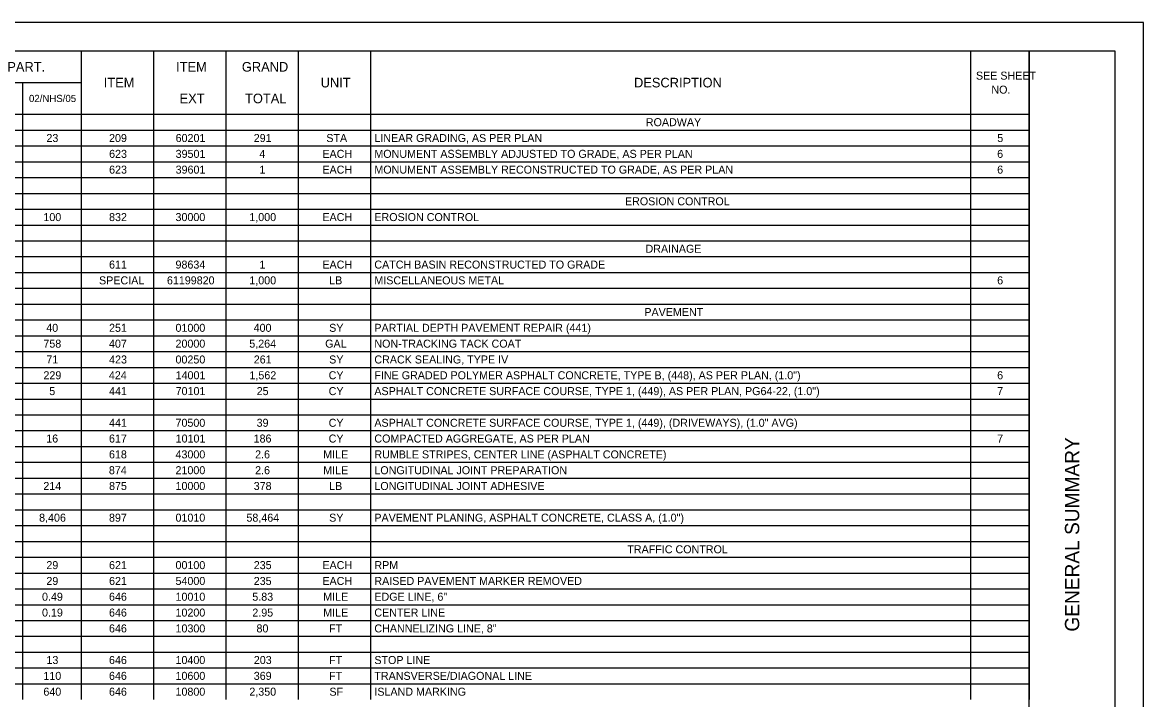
# Model space of a CAD drawing. Extents: x 0 to 34, y 0 to 22.
# Drawn here: x 14.4 to 34, y 10.16 to 22 of the extents above; entities that cross this region are included whole.
import ezdxf

# ---------------------------------------------------------------- set-up
doc = ezdxf.new("R2010")
doc.units = 0
for name, color, linetype in [('Default', 7, 'Continuous'), ('SH_Border', 7, 'Continuous'), ('SH_Cut_Line', 7, 'Continuous'), ('SH_Data', 7, 'Continuous')]:
    doc.layers.add(name, color=color, linetype=linetype)

msp = doc.modelspace()

# ---------------------------------------------------------------- linework, layer by layer
at = {"layer": 'Default'}
for p, q in [((13.368, 21.5), (14.396, 21.5)), ((14.396, 21.5), (30.972, 21.5)), ((15.424, 21.5), (15.424, 21.223)), ((16.689, 21.5), (16.689, 21.223)), ((17.954, 21.5), (17.954, 21.223)), ((19.219, 21.5), (19.219, 21.223)), ((20.484, 21.5), (20.484, 21.223)), ((30.972, 21.5), (32, 21.5)), ((30.972, 21.5), (30.972, 21.223)), ((32, 21.5), (32, 21.223)), ((15.424, 21.223), (15.424, 20.947)), ((16.689, 21.223), (16.689, 20.947)), ((17.954, 21.223), (17.954, 20.947)), ((19.219, 21.223), (19.219, 20.947)), ((20.484, 21.223), (20.484, 20.947)), ((30.972, 21.223), (30.972, 20.947)), ((32, 21.223), (32, 20.947)), ((13.368, 20.947), (14.396, 20.947)), ((14.396, 20.947), (15.424, 20.947)), ((14.396, 20.947), (14.396, 20.67)), ((15.424, 20.947), (15.424, 20.67)), ((16.689, 20.947), (16.689, 20.67)), ((17.954, 20.947), (17.954, 20.67)), ((19.219, 20.947), (19.219, 20.67)), ((20.484, 20.947), (20.484, 20.67)), ((30.972, 20.947), (30.972, 20.67)), ((32, 20.947), (32, 20.67)), ((14.396, 20.67), (14.396, 20.393)), ((15.424, 20.67), (15.424, 20.393)), ((16.689, 20.67), (16.689, 20.393)), ((17.954, 20.67), (17.954, 20.393)), ((19.219, 20.67), (19.219, 20.393)), ((20.484, 20.67), (20.484, 20.393)), ((30.972, 20.67), (30.972, 20.393)), ((32, 20.67), (32, 20.393)), ((13.368, 20.393), (14.396, 20.393)), ((14.396, 20.393), (30.972, 20.393)), ((14.396, 20.393), (14.396, 20.116)), ((15.424, 20.393), (15.424, 20.116)), ((16.689, 20.393), (16.689, 20.116)), ((17.954, 20.393), (17.954, 20.116)), ((19.219, 20.393), (19.219, 20.116)), ((20.484, 20.393), (20.484, 20.116)), ((30.972, 20.393), (32, 20.393)), ((30.972, 20.393), (30.972, 20.116)), ((32, 20.393), (32, 20.116)), ((13.368, 20.116), (14.396, 20.116)), ((14.396, 20.116), (30.972, 20.116)), ((14.396, 20.116), (14.396, 18.733)), ((15.424, 20.116), (15.424, 18.733)), ((16.689, 20.116), (16.689, 18.733)), ((17.954, 20.116), (17.954, 18.733)), ((19.219, 20.116), (19.219, 18.733)), ((20.484, 20.116), (20.484, 18.733)), ((30.972, 20.116), (32, 20.116)), ((30.972, 20.116), (30.972, 18.733)), ((32, 20.116), (32, 18.733)), ((13.368, 19.84), (14.396, 19.84)), ((14.396, 19.84), (30.972, 19.84)), ((30.972, 19.84), (32, 19.84)), ((13.368, 19.563), (14.396, 19.563)), ((14.396, 19.563), (30.972, 19.563)), ((30.972, 19.563), (32, 19.563)), ((13.368, 19.286), (14.396, 19.286)), ((14.396, 19.286), (30.972, 19.286)), ((30.972, 19.286), (32, 19.286)), ((13.368, 19.01), (14.396, 19.01)), ((14.396, 19.01), (30.972, 19.01)), ((30.972, 19.01), (32, 19.01)), ((13.368, 18.733), (14.396, 18.733)), ((14.396, 18.733), (30.972, 18.733)), ((14.396, 18.733), (14.396, 18.18)), ((15.424, 18.733), (15.424, 18.18)), ((16.689, 18.733), (16.689, 18.18)), ((17.954, 18.733), (17.954, 18.18)), ((19.219, 18.733), (19.219, 18.18)), ((20.484, 18.733), (20.484, 18.18)), ((30.972, 18.733), (32, 18.733)), ((30.972, 18.733), (30.972, 18.18)), ((32, 18.733), (32, 18.18)), ((13.368, 18.456), (14.396, 18.456)), ((14.396, 18.456), (30.972, 18.456)), ((30.972, 18.456), (32, 18.456)), ((13.368, 18.18), (14.396, 18.18)), ((14.396, 18.18), (30.972, 18.18)), ((14.396, 18.18), (14.396, 17.903)), ((15.424, 18.18), (15.424, 17.903)), ((16.689, 18.18), (16.689, 17.903)), ((17.954, 18.18), (17.954, 17.903)), ((19.219, 18.18), (19.219, 17.903)), ((20.484, 18.18), (20.484, 17.903)), ((30.972, 18.18), (32, 18.18)), ((30.972, 18.18), (30.972, 17.903)), ((32, 18.18), (32, 17.903)), ((13.368, 17.903), (14.396, 17.903)), ((14.396, 17.903), (30.972, 17.903)), ((14.396, 17.903), (14.396, 17.626)), ((15.424, 17.903), (15.424, 17.626)), ((16.689, 17.903), (16.689, 17.626)), ((17.954, 17.903), (17.954, 17.626)), ((19.219, 17.903), (19.219, 17.626)), ((20.484, 17.903), (20.484, 17.626)), ((30.972, 17.903), (32, 17.903)), ((30.972, 17.903), (30.972, 17.626)), ((32, 17.903), (32, 17.626)), ((13.368, 17.626), (14.396, 17.626)), ((14.396, 17.626), (30.972, 17.626)), ((14.396, 17.626), (14.396, 17.349)), ((15.424, 17.626), (15.424, 17.349)), ((16.689, 17.626), (16.689, 17.349)), ((17.954, 17.626), (17.954, 17.349)), ((19.219, 17.626), (19.219, 17.349)), ((20.484, 17.626), (20.484, 17.349)), ((30.972, 17.626), (32, 17.626)), ((30.972, 17.626), (30.972, 17.349)), ((32, 17.626), (32, 17.349)), ((13.368, 17.349), (14.396, 17.349)), ((14.396, 17.349), (30.972, 17.349)), ((14.396, 17.349), (14.396, 17.073)), ((15.424, 17.349), (15.424, 17.073)), ((16.689, 17.349), (16.689, 17.073)), ((17.954, 17.349), (17.954, 17.073)), ((19.219, 17.349), (19.219, 17.073)), ((20.484, 17.349), (20.484, 17.073)), ((30.972, 17.349), (32, 17.349)), ((30.972, 17.349), (30.972, 17.073)), ((32, 17.349), (32, 17.073)), ((13.368, 17.073), (14.396, 17.073)), ((14.396, 17.073), (30.972, 17.073)), ((14.396, 17.073), (14.396, 16.796)), ((15.424, 17.073), (15.424, 16.796)), ((16.689, 17.073), (16.689, 16.796)), ((17.954, 17.073), (17.954, 16.796)), ((19.219, 17.073), (19.219, 16.796)), ((20.484, 17.073), (20.484, 16.796)), ((30.972, 17.073), (32, 17.073)), ((30.972, 17.073), (30.972, 16.796)), ((32, 17.073), (32, 16.796)), ((13.368, 16.796), (14.396, 16.796)), ((14.396, 16.796), (30.972, 16.796)), ((14.396, 16.796), (14.396, 16.243)), ((15.424, 16.796), (15.424, 16.243)), ((16.689, 16.796), (16.689, 16.243)), ((17.954, 16.796), (17.954, 16.243)), ((19.219, 16.796), (19.219, 16.243)), ((20.484, 16.796), (20.484, 16.243)), ((30.972, 16.796), (32, 16.796)), ((30.972, 16.796), (30.972, 16.243)), ((32, 16.796), (32, 16.243)), ((13.368, 16.519), (14.396, 16.519)), ((14.396, 16.519), (30.972, 16.519)), ((30.972, 16.519), (32, 16.519)), ((13.368, 16.243), (14.396, 16.243)), ((14.396, 16.243), (30.972, 16.243)), ((14.396, 16.243), (14.396, 15.966)), ((15.424, 16.243), (15.424, 15.966)), ((16.689, 16.243), (16.689, 15.966)), ((17.954, 16.243), (17.954, 15.966)), ((19.219, 16.243), (19.219, 15.966)), ((20.484, 16.243), (20.484, 15.966)), ((30.972, 16.243), (32, 16.243)), ((30.972, 16.243), (30.972, 15.966)), ((32, 16.243), (32, 15.966)), ((13.368, 15.966), (14.396, 15.966)), ((14.396, 15.966), (30.972, 15.966)), ((14.396, 15.966), (14.396, 15.689)), ((15.424, 15.966), (15.424, 15.689)), ((16.689, 15.966), (16.689, 15.689)), ((17.954, 15.966), (17.954, 15.689)), ((19.219, 15.966), (19.219, 15.689)), ((20.484, 15.966), (20.484, 15.689)), ((30.972, 15.966), (32, 15.966)), ((30.972, 15.966), (30.972, 15.689)), ((32, 15.966), (32, 15.689)), ((13.368, 15.689), (14.396, 15.689)), ((14.396, 15.689), (30.972, 15.689)), ((14.396, 15.689), (14.396, 15.412)), ((15.424, 15.689), (15.424, 15.412)), ((16.689, 15.689), (16.689, 15.412)), ((17.954, 15.689), (17.954, 15.412)), ((19.219, 15.689), (19.219, 15.412)), ((20.484, 15.689), (20.484, 15.412)), ((30.972, 15.689), (32, 15.689)), ((30.972, 15.689), (30.972, 15.412)), ((32, 15.689), (32, 15.412)), ((13.368, 15.412), (14.396, 15.412)), ((14.396, 15.412), (30.972, 15.412)), ((14.396, 15.412), (14.396, 14.859)), ((15.424, 15.412), (15.424, 14.859)), ((16.689, 15.412), (16.689, 14.859)), ((17.954, 15.412), (17.954, 14.859)), ((19.219, 15.412), (19.219, 14.859)), ((20.484, 15.412), (20.484, 14.859)), ((30.972, 15.412), (32, 15.412)), ((30.972, 15.412), (30.972, 14.859)), ((32, 15.412), (32, 14.859)), ((13.368, 15.136), (14.396, 15.136)), ((14.396, 15.136), (30.972, 15.136)), ((30.972, 15.136), (32, 15.136)), ((13.368, 14.859), (14.396, 14.859)), ((14.396, 14.859), (30.972, 14.859)), ((14.396, 14.859), (14.396, 14.582)), ((15.424, 14.859), (15.424, 14.582)), ((16.689, 14.859), (16.689, 14.582)), ((17.954, 14.859), (17.954, 14.582)), ((19.219, 14.859), (19.219, 14.582)), ((20.484, 14.859), (20.484, 14.582)), ((30.972, 14.859), (32, 14.859)), ((30.972, 14.859), (30.972, 14.582)), ((32, 14.859), (32, 14.582)), ((13.368, 14.582), (14.396, 14.582)), ((14.396, 14.582), (30.972, 14.582)), ((14.396, 14.582), (14.396, 14.306)), ((15.424, 14.582), (15.424, 14.306)), ((16.689, 14.582), (16.689, 14.306)), ((17.954, 14.582), (17.954, 14.306)), ((19.219, 14.582), (19.219, 14.306)), ((20.484, 14.582), (20.484, 14.306)), ((30.972, 14.582), (32, 14.582)), ((30.972, 14.582), (30.972, 14.306)), ((32, 14.582), (32, 14.306)), ((13.368, 14.306), (14.396, 14.306)), ((14.396, 14.306), (30.972, 14.306)), ((14.396, 14.306), (14.396, 14.029)), ((15.424, 14.306), (15.424, 14.029)), ((16.689, 14.306), (16.689, 14.029)), ((17.954, 14.306), (17.954, 14.029)), ((19.219, 14.306), (19.219, 14.029)), ((20.484, 14.306), (20.484, 14.029)), ((30.972, 14.306), (32, 14.306)), ((30.972, 14.306), (30.972, 14.029)), ((32, 14.306), (32, 14.029)), ((13.368, 14.029), (14.396, 14.029)), ((14.396, 14.029), (30.972, 14.029)), ((14.396, 14.029), (14.396, 11.815)), ((15.424, 14.029), (15.424, 11.815)), ((16.689, 14.029), (16.689, 11.815)), ((17.954, 14.029), (17.954, 11.815)), ((19.219, 14.029), (19.219, 11.815)), ((20.484, 14.029), (20.484, 11.815)), ((30.972, 14.029), (32, 14.029)), ((30.972, 14.029), (30.972, 11.815)), ((32, 14.029), (32, 11.815)), ((13.368, 13.752), (14.396, 13.752)), ((14.396, 13.752), (30.972, 13.752)), ((30.972, 13.752), (32, 13.752)), ((13.368, 13.476), (14.396, 13.476)), ((14.396, 13.476), (30.972, 13.476)), ((30.972, 13.476), (32, 13.476)), ((13.368, 13.199), (14.396, 13.199)), ((14.396, 13.199), (30.972, 13.199)), ((30.972, 13.199), (32, 13.199)), ((13.368, 12.922), (14.396, 12.922)), ((14.396, 12.922), (30.972, 12.922)), ((30.972, 12.922), (32, 12.922)), ((13.368, 12.645), (14.396, 12.645)), ((14.396, 12.645), (30.972, 12.645)), ((30.972, 12.645), (32, 12.645)), ((13.368, 12.369), (14.396, 12.369)), ((14.396, 12.369), (30.972, 12.369)), ((30.972, 12.369), (32, 12.369)), ((13.368, 12.092), (14.396, 12.092)), ((14.396, 12.092), (30.972, 12.092)), ((30.972, 12.092), (32, 12.092)), ((13.368, 11.815), (14.396, 11.815)), ((14.396, 11.815), (30.972, 11.815)), ((14.396, 11.815), (14.396, 11.539)), ((15.424, 11.815), (15.424, 11.539)), ((16.689, 11.815), (16.689, 11.539)), ((17.954, 11.815), (17.954, 11.539)), ((19.219, 11.815), (19.219, 11.539)), ((20.484, 11.815), (20.484, 11.539)), ((30.972, 11.815), (32, 11.815)), ((30.972, 11.815), (30.972, 11.539)), ((32, 11.815), (32, 11.539)), ((13.368, 11.539), (14.396, 11.539)), ((14.396, 11.539), (30.972, 11.539)), ((14.396, 11.539), (14.396, 10.432)), ((15.424, 11.539), (15.424, 10.432)), ((16.689, 11.539), (16.689, 10.432)), ((17.954, 11.539), (17.954, 10.432)), ((19.219, 11.539), (19.219, 10.432)), ((20.484, 11.539), (20.484, 10.432)), ((30.972, 11.539), (32, 11.539)), ((30.972, 11.539), (30.972, 10.432)), ((32, 11.539), (32, 10.432)), ((13.368, 11.262), (14.396, 11.262)), ((14.396, 11.262), (30.972, 11.262)), ((30.972, 11.262), (32, 11.262)), ((13.368, 10.985), (14.396, 10.985)), ((14.396, 10.985), (30.972, 10.985)), ((30.972, 10.985), (32, 10.985)), ((13.368, 10.708), (14.396, 10.708)), ((14.396, 10.708), (30.972, 10.708)), ((30.972, 10.708), (32, 10.708)), ((13.368, 10.432), (14.396, 10.432)), ((14.396, 10.432), (30.972, 10.432)), ((14.396, 10.432), (14.396, 10.155)), ((15.424, 10.432), (15.424, 10.155)), ((16.689, 10.432), (16.689, 10.155)), ((17.954, 10.432), (17.954, 10.155)), ((19.219, 10.432), (19.219, 10.155)), ((20.484, 10.432), (20.484, 10.155)), ((30.972, 10.432), (32, 10.432)), ((30.972, 10.432), (30.972, 10.155)), ((32, 10.432), (32, 10.155))]:
    msp.add_line(p, q, dxfattribs=at)
at = {"layer": 'SH_Border'}
msp.add_line((32, 0.5), (32, 21.5), dxfattribs=at)
msp.add_lwpolyline([(1.5, 21.5), (33.5, 21.5), (33.5, 0.5), (1.5, 0.5)], close=True, dxfattribs=at)
at = {"layer": 'SH_Cut_Line'}
msp.add_lwpolyline([(0, 0), (34, 0), (34, 22), (0, 22)], close=True, dxfattribs=at)

# ---------------------------------------------------------------- texts
at = {"layer": 'Default'}
for s, height, p in [('PART.', 0.168, (14.132, 21.139)), ('ITEM', 0.168, (17.083, 21.139)), ('GRAND', 0.168, (18.233, 21.139)), ('ITEM', 0.168, (15.818, 20.863)), ('UNIT', 0.168, (19.611, 20.863)), ('DESCRIPTION', 0.168, (25.09, 20.863)), ('SEE SHEET ', 0.14, (31.069, 20.999)), ('NO.', 0.14, (31.339, 20.754)), ('02/NHS/05', 0.126, (14.511, 20.607)), ('EXT', 0.168, (17.144, 20.586)), ('TOTAL', 0.168, (18.289, 20.586)), ('ROADWAY', 0.14, (25.297, 20.185)), ('23', 0.14, (14.816, 19.908)), ('209', 0.14, (15.911, 19.908)), ('60201', 0.14, (17.075, 19.908)), ('291', 0.14, (18.441, 19.908)), ('STA', 0.14, (19.71, 19.908)), ('LINEAR GRADING, AS PER PLAN', 0.14, (20.55, 19.908)), ('5', 0.14, (31.442, 19.908)), ('623', 0.14, (15.912, 19.631)), ('39501', 0.14, (17.075, 19.631)), ('4', 0.14, (18.539, 19.631)), ('EACH', 0.14, (19.641, 19.631)), ('MONUMENT ASSEMBLY ADJUSTED TO GRADE, AS PER PLAN', 0.14, (20.55, 19.631)), ('6', 0.14, (31.44, 19.631)), ('623', 0.14, (15.912, 19.355)), ('39601', 0.14, (17.075, 19.355)), ('1', 0.14, (18.541, 19.355)), ('EACH', 0.14, (19.641, 19.355)), ('MONUMENT ASSEMBLY RECONSTRUCTED TO GRADE, AS PER PLAN', 0.14, (20.55, 19.355)), ('6', 0.14, (31.44, 19.355)), ('EROSION CONTROL', 0.14, (24.932, 18.801)), ('100', 0.14, (14.763, 18.525)), ('832', 0.14, (15.911, 18.525)), ('30000', 0.14, (17.073, 18.525)), ('1,000', 0.14, (18.364, 18.525)), ('EACH', 0.14, (19.641, 18.525)), ('EROSION CONTROL', 0.14, (20.55, 18.525)), ('DRAINAGE', 0.14, (25.291, 17.971)), ('611', 0.14, (15.911, 17.694)), ('98634', 0.14, (17.073, 17.694)), ('1', 0.14, (18.541, 17.694)), ('EACH', 0.14, (19.641, 17.694)), ('CATCH BASIN RECONSTRUCTED TO GRADE', 0.14, (20.55, 17.694)), ('SPECIAL', 0.14, (15.736, 17.418)), ('61199820', 0.14, (16.923, 17.418)), ('1,000', 0.14, (18.364, 17.418)), ('LB', 0.14, (19.76, 17.418)), ('MISCELLANEOUS METAL', 0.14, (20.55, 17.418)), ('6', 0.14, (31.44, 17.418)), ('PAVEMENT', 0.14, (25.271, 16.864)), ('40', 0.14, (14.813, 16.588)), ('251', 0.14, (15.911, 16.588)), ('01000', 0.14, (17.073, 16.588)), ('400', 0.14, (18.439, 16.588)), ('SY', 0.14, (19.76, 16.588)), ('PARTIAL DEPTH PAVEMENT REPAIR (441)', 0.14, (20.55, 16.588)), ('758', 0.14, (14.763, 16.311)), ('407', 0.14, (15.91, 16.311)), ('20000', 0.14, (17.073, 16.311)), ('5,264', 0.14, (18.363, 16.311)), ('GAL', 0.14, (19.69, 16.311)), ('NON-TRACKING TACK COAT', 0.14, (20.55, 16.311)), ('71', 0.14, (14.815, 16.034)), ('423', 0.14, (15.912, 16.034)), ('00250', 0.14, (17.073, 16.034)), ('261', 0.14, (18.441, 16.034)), ('SY', 0.14, (19.76, 16.034)), ('CRACK SEALING, TYPE IV', 0.14, (20.55, 16.034)), ('229', 0.14, (14.764, 15.758)), ('424', 0.14, (15.908, 15.758)), ('14001', 0.14, (17.075, 15.758)), ('1,562', 0.14, (18.366, 15.758)), ('CY', 0.14, (19.751, 15.758)), ('FINE GRADED POLYMER ASPHALT CONCRETE, TYPE B, (448), AS PER PLAN, (1.0")', 0.14, (20.55, 15.758)), ('6', 0.14, (31.44, 15.758)), ('5', 0.14, (14.866, 15.481)), ('441', 0.14, (15.911, 15.481)), ('70101', 0.14, (17.075, 15.481)), ('25', 0.14, (18.492, 15.481)), ('CY', 0.14, (19.751, 15.481)), ('ASPHALT CONCRETE SURFACE COURSE, TYPE 1, (449), AS PER PLAN, PG64-22, (1.0")', 0.14, (20.55, 15.481)), ('7', 0.14, (31.44, 15.481)), ('441', 0.14, (15.911, 14.927)), ('70500', 0.14, (17.073, 14.927)), ('39', 0.14, (18.491, 14.927)), ('CY', 0.14, (19.751, 14.927)), ('ASPHALT CONCRETE SURFACE COURSE, TYPE 1, (449), (DRIVEWAYS), (1.0" AVG)', 0.14, (20.55, 14.927)), ('16', 0.14, (14.813, 14.651)), ('617', 0.14, (15.91, 14.651)), ('10101', 0.14, (17.075, 14.651)), ('186', 0.14, (18.439, 14.651)), ('CY', 0.14, (19.751, 14.651)), ('COMPACTED AGGREGATE, AS PER PLAN', 0.14, (20.55, 14.651)), ('7', 0.14, (31.44, 14.651)), ('618', 0.14, (15.91, 14.374)), ('43000', 0.14, (17.073, 14.374)), ('2.6', 0.14, (18.465, 14.374)), ('MILE', 0.14, (19.656, 14.374)), ('RUMBLE STRIPES, CENTER LINE (ASPHALT CONCRETE)', 0.14, (20.55, 14.374)), ('874', 0.14, (15.908, 14.097)), ('21000', 0.14, (17.073, 14.097)), ('2.6', 0.14, (18.465, 14.097)), ('MILE', 0.14, (19.656, 14.097)), ('LONGITUDINAL JOINT PREPARATION', 0.14, (20.55, 14.097)), ('214', 0.14, (14.762, 13.821)), ('875', 0.14, (15.911, 13.821)), ('10000', 0.14, (17.073, 13.821)), ('378', 0.14, (18.44, 13.821)), ('LB', 0.14, (19.76, 13.821)), ('LONGITUDINAL JOINT ADHESIVE', 0.14, (20.55, 13.821)), ('8,406', 0.14, (14.688, 13.267)), ('897', 0.14, (15.91, 13.267)), ('01010', 0.14, (17.073, 13.267)), ('58,464', 0.14, (18.313, 13.267)), ('SY', 0.14, (19.76, 13.267)), ('PAVEMENT PLANING, ASPHALT CONCRETE, CLASS A, (1.0")', 0.14, (20.55, 13.267)), ('TRAFFIC CONTROL', 0.14, (24.973, 12.714)), ('29', 0.14, (14.815, 12.437)), ('621', 0.14, (15.911, 12.437)), ('00100', 0.14, (17.073, 12.437)), ('235', 0.14, (18.441, 12.437)), ('EACH', 0.14, (19.641, 12.437)), ('RPM', 0.14, (20.55, 12.437)), ('29', 0.14, (14.815, 12.16)), ('621', 0.14, (15.911, 12.16)), ('54000', 0.14, (17.073, 12.16)), ('235', 0.14, (18.441, 12.16)), ('EACH', 0.14, (19.641, 12.16)), ('RAISED PAVEMENT MARKER REMOVED', 0.14, (20.55, 12.16)), ('0.49', 0.14, (14.739, 11.884)), ('646', 0.14, (15.91, 11.884)), ('10010', 0.14, (17.073, 11.884)), ('5.83', 0.14, (18.416, 11.884)), ('MILE', 0.14, (19.656, 11.884)), ('EDGE LINE, 6"', 0.14, (20.55, 11.884)), ('0.19', 0.14, (14.739, 11.607)), ('646', 0.14, (15.91, 11.607)), ('10200', 0.14, (17.073, 11.607)), ('2.95', 0.14, (18.416, 11.607)), ('MILE', 0.14, (19.656, 11.607)), ('CENTER LINE', 0.14, (20.55, 11.607)), ('646', 0.14, (15.91, 11.33)), ('10300', 0.14, (17.073, 11.33)), ('80', 0.14, (18.489, 11.33)), ('FT', 0.14, (19.758, 11.33)), ('CHANNELIZING LINE, 8"', 0.14, (20.55, 11.33)), ('13', 0.14, (14.816, 10.777)), ('646', 0.14, (15.91, 10.777)), ('10400', 0.14, (17.073, 10.777)), ('203', 0.14, (18.442, 10.777)), ('FT', 0.14, (19.758, 10.777)), ('STOP LINE', 0.14, (20.55, 10.777)), ('110', 0.14, (14.763, 10.5)), ('646', 0.14, (15.91, 10.5)), ('10600', 0.14, (17.073, 10.5)), ('369', 0.14, (18.441, 10.5)), ('FT', 0.14, (19.758, 10.5)), ('TRANSVERSE/DIAGONAL LINE', 0.14, (20.55, 10.5)), ('640', 0.14, (14.763, 10.223)), ('646', 0.14, (15.91, 10.223)), ('10800', 0.14, (17.073, 10.223)), ('2,350', 0.14, (18.364, 10.223)), ('SF', 0.14, (19.764, 10.223)), ('ISLAND MARKING', 0.14, (20.55, 10.223))]:
    msp.add_text(s, height=height, dxfattribs=at).set_placement(p)
at = {"layer": 'SH_Data'}
msp.add_text('GENERAL SUMMARY', height=0.25, rotation=90, dxfattribs=at).set_placement((32.875, 11.344))

doc.saveas('drawing.dxf')
